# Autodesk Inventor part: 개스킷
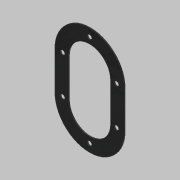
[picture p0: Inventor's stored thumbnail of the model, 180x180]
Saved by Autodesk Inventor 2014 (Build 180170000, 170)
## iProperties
Created: 2019-03
Part Number: 개스킷
Material: 고무
Document SubType Name: Modeling
Designer: mduedu
Density: 1 g/cm^3
Appearance: 고무 - 검은색 - 버전 1.1
Author: mduedu
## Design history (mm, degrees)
sketch "스케치1"
  geometry: L1 (-62, 40)-(62, 40); L2 (62, 40)-(62, -40); L3 (62, -40)-(-62, -40); L4 (-62, -40)-(-62, 40); L5 (-62, 40)-(62, -40); L6 (62, 40)-(-62, -40); 1 further point
  constraints: 12 end point, 2 midpoint, 2 parallel, 1 horizontal, 1 perpendicular
  dimensions: "d21" = 124 distance of L2.end L3.end; "d22" = 80 distance of L1.end L2.end
extrude "돌출1" new body sketch "스케치1" distance "d3" = 1; taper "d4" = 0 deg
fillet "모깎기2"
fillet "모깎기3"
sketch "스케치2" dims "d6" = 48
  geometry: L1 (-24, -22)-(24, -22); L2 (24, -22)-(24, 22); L3 (24, 22)-(-24, 22); L4 (-24, 22)-(-24, -22); L5 (-24, -22)-(24, 22); L6 (24, -22)-(-24, 22); 3 further points
  constraints: 12 end point, 4 midpoint, 2 horizontal alignment, 2 parallel, 1 horizontal, 1 perpendicular, 4 other
  dimensions: "d8" = 22 distance from line of L3 point (0, 0)
extrude "돌출2" cut sketch "스케치2" stored distance "d9" = 1; taper "d10" = 0 deg
sketch "스케치3"
  geometry: L1 (24, -22)-(24, 22) reference; L2 (-24, 22)-(-24, -22) reference; L3 (31, 22)-(31, -22); L4 (-31, -22)-(-31, 22); A1 r 24 centre (0, 22) between (24, 22) and (-24, 22) reference; A2 r 24 centre (0, -22) between (-24, -22) and (24, -22) reference; A3 r 31 centre (0, 22) between (31, 22) and (-31, 22); A4 r 31 centre (0, -22) between (-31, -22) and (31, -22); 7 further points
  constraints: 6 point on circle, 4 coincident, 4 end point, 2 centre point, 3 other
  dimensions: "d26" = 62 distance between parallel lines of L3 L4; "d28" = 7 distance between parallel lines of L4 L2 (derived); "d29" = 48 distance between parallel lines of L1 L2 (derived); "d30" = 31 radius of A3 (derived)
hole "구멍1" sketch "스케치3" at (0, 53), (31, 22), (31, -22), (0, -53), (-31, -22), (-31, 22) diameter "d14" = 5; stored, may be unused: countersink angle "d18" = 90 deg, drill point angle "d20" = 118 deg; dims "d15" = 6, "d16" = 4, "d17" = 2, "d19" = 8
node "솔리드1"
